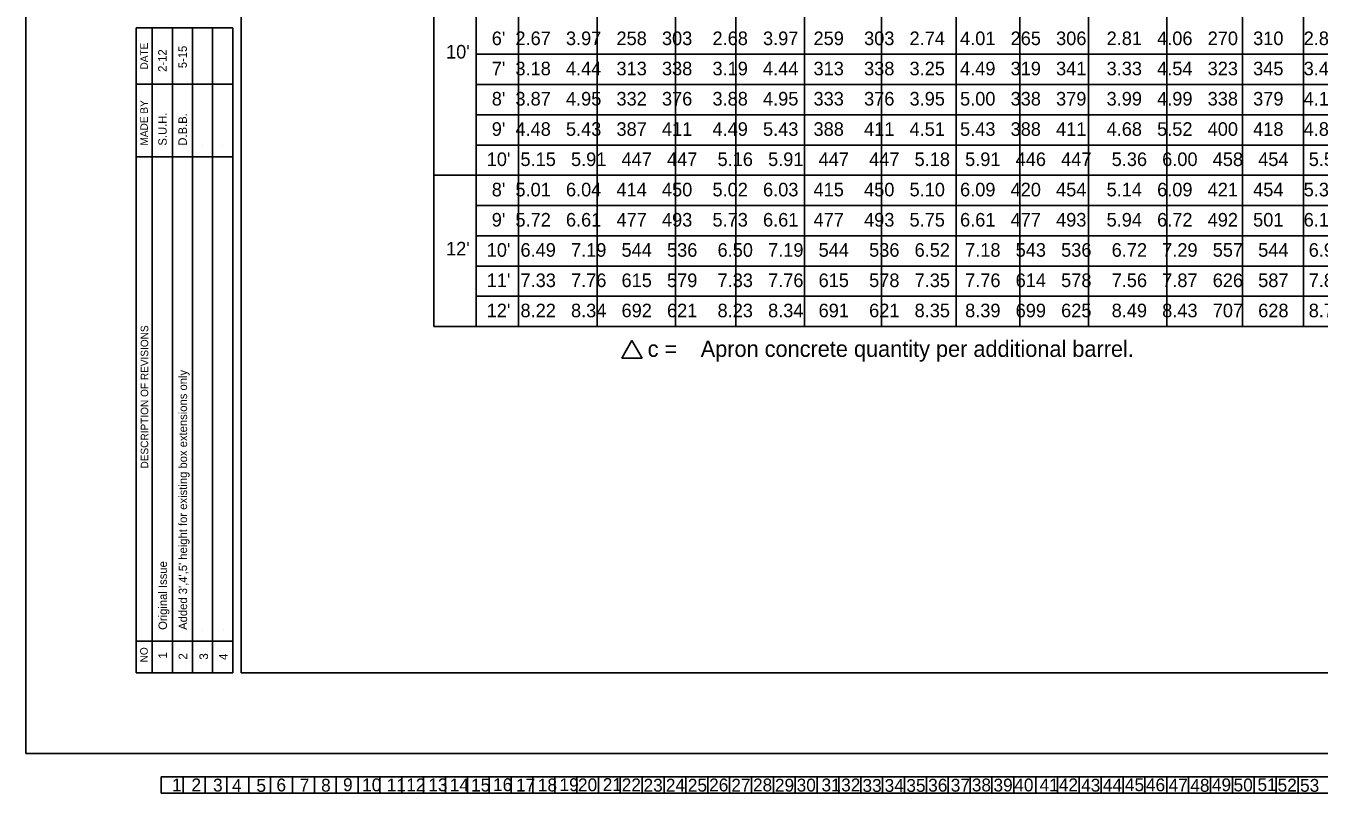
# Model space of a CAD drawing. Extents: x -0.08 to 2.83, y -0.03 to 1.92.
# Drawn here: x 0 to 1.002, y -0.031 to 0.564 of the extents above; entities that cross this region are included whole.
import ezdxf

# ---------------------------------------------------------------- set-up
doc = ezdxf.new("R2010")
doc.units = 0
for name, color, linetype in [('1', 7, 'Continuous'), ('10', 7, 'Continuous'), ('11', 7, 'Continuous'), ('12', 7, 'Continuous'), ('13', 7, 'Continuous'), ('14', 7, 'Continuous'), ('15', 7, 'Continuous'), ('16', 7, 'Continuous'), ('17', 7, 'Continuous'), ('18', 7, 'Continuous'), ('19', 7, 'Continuous'), ('2', 7, 'Continuous'), ('20', 7, 'Continuous'), ('21', 7, 'Continuous'), ('22', 7, 'Continuous'), ('23', 7, 'Continuous'), ('24', 7, 'Continuous'), ('25', 7, 'Continuous'), ('26', 7, 'Continuous'), ('27', 7, 'Continuous'), ('28', 7, 'Continuous'), ('29', 7, 'Continuous'), ('3', 7, 'Continuous'), ('30', 7, 'Continuous'), ('31', 7, 'Continuous'), ('32', 7, 'Continuous'), ('33', 7, 'Continuous'), ('34', 7, 'Continuous'), ('35', 7, 'Continuous'), ('36', 7, 'Continuous'), ('37', 7, 'Continuous'), ('38', 7, 'Continuous'), ('39', 7, 'Continuous'), ('4', 7, 'Continuous'), ('40', 7, 'Continuous'), ('41', 7, 'Continuous'), ('42', 7, 'Continuous'), ('43', 7, 'Continuous'), ('44', 7, 'Continuous'), ('45', 7, 'Continuous'), ('46', 7, 'Continuous'), ('47', 7, 'Continuous'), ('48', 7, 'Continuous'), ('49', 7, 'Continuous'), ('5', 7, 'Continuous'), ('50', 7, 'Continuous'), ('51', 7, 'Continuous'), ('52', 7, 'Continuous'), ('53', 7, 'Continuous'), ('55', 7, 'Continuous'), ('57', 7, 'Continuous'), ('6', 7, 'Continuous'), ('62', 7, 'Continuous'), ('63', 7, 'Continuous'), ('7', 7, 'Continuous'), ('8', 7, 'Continuous'), ('9', 7, 'Continuous')]:
    doc.layers.add(name, color=color, linetype=linetype)

msp = doc.modelspace()

# ---------------------------------------------------------------- linework, layer by layer
at = {"layer": '49'}
for p, q in [((0.6032, 0.9636), (0.6032, 0.3308)), ((0.8233, 0.9636), (0.8233, 0.3308)), ((0.3161, 0.448), (2.5857, 0.448))]:
    msp.add_line(p, q, dxfattribs=at)
at = {"layer": '55'}
for p, q in [((0.3161, 0.9949), (0.3161, 0.3308)), ((0.3489, 0.9636), (0.3489, 0.3308)), ((0.3817, 0.9636), (0.3817, 0.3308)), ((0.5033, 0.9402), (0.5033, 0.3308)), ((0.7208, 0.9402), (0.7208, 0.3308)), ((0.9426, 0.9402), (0.9426, 0.3308)), ((0.4426, 0.9168), (0.4426, 0.3308)), ((0.55, 0.9168), (0.55, 0.3308)), ((0.6628, 0.9168), (0.6628, 0.3308)), ((0.7701, 0.9168), (0.7701, 0.3308)), ((0.884, 0.9168), (0.884, 0.3308)), ((0.9897, 0.9168), (0.9897, 0.3308)), ((0.3489, 0.5418), (2.5857, 0.5418)), ((0.3489, 0.5183), (2.5857, 0.5183)), ((0.3489, 0.4949), (2.5857, 0.4949)), ((0.3489, 0.4714), (2.5857, 0.4714)), ((0.3489, 0.4246), (2.5857, 0.4246)), ((0.3489, 0.4011), (2.5857, 0.4011)), ((0.3489, 0.3777), (2.5857, 0.3777)), ((0.3489, 0.3543), (2.5857, 0.3543)), ((0.3161, 0.3308), (2.5857, 0.3308)), ((0.3489, 0.3308), (2.5857, 0.3308))]:
    msp.add_line(p, q, dxfattribs=at)
at = {"layer": '57'}
for p, q in [((0.4695, 0.3201), (0.4616, 0.3064)), ((0.4774, 0.3064), (0.4695, 0.3201)), ((0.4616, 0.3064), (0.4774, 0.3064))]:
    msp.add_line(p, q, dxfattribs=at)
at = {"layer": '62'}
for p, q in [((0.1058, 0.471), (0.1058, 0.471)), ((0.1219, 0.471), (0.1219, 0.471)), ((0.1372, 0.471), (0.1372, 0.471)), ((0.1525, 0.471), (0.1525, 0.471)), ((0.106, 0.0958), (0.106, 0.0958)), ((0.121, 0.0954), (0.121, 0.0954)), ((0.1367, 0.0954), (0.1367, 0.0954)), ((0.153, 0.0958), (0.153, 0.0958)), ((0.1049, -0.018), (1.1717, -0.018)), ((0.1049, -0.018), (0.1049, -0.0307)), ((0.1219, -0.018), (0.1219, -0.0307)), ((0.1388, -0.018), (0.1388, -0.0307)), ((0.1557, -0.018), (0.1557, -0.0307)), ((0.1727, -0.018), (0.1727, -0.0307)), ((0.1896, -0.018), (0.1896, -0.0307)), ((0.2065, -0.018), (0.2065, -0.0307)), ((0.2235, -0.018), (0.2235, -0.0307)), ((0.2404, -0.018), (0.2404, -0.0307)), ((0.2573, -0.018), (0.2573, -0.0307)), ((0.2743, -0.018), (0.2743, -0.0307)), ((0.2912, -0.018), (0.2912, -0.0307)), ((0.3081, -0.018), (0.3081, -0.0307)), ((0.3251, -0.018), (0.3251, -0.0307)), ((0.342, -0.018), (0.342, -0.0307)), ((0.3589, -0.018), (0.3589, -0.0307)), ((0.3759, -0.018), (0.3759, -0.0307)), ((0.3928, -0.018), (0.3928, -0.0307)), ((0.4097, -0.018), (0.4097, -0.0307)), ((0.4267, -0.018), (0.4267, -0.0307)), ((0.4436, -0.018), (0.4436, -0.0307)), ((0.4605, -0.018), (0.4605, -0.0307)), ((0.4775, -0.018), (0.4775, -0.0307)), ((0.4944, -0.018), (0.4944, -0.0307)), ((0.5113, -0.018), (0.5113, -0.0307)), ((0.5283, -0.018), (0.5283, -0.0307)), ((0.5452, -0.018), (0.5452, -0.0307)), ((0.5621, -0.018), (0.5621, -0.0307)), ((0.5791, -0.018), (0.5791, -0.0307)), ((0.596, -0.018), (0.596, -0.0307)), ((0.6129, -0.018), (0.6129, -0.0307)), ((0.6299, -0.018), (0.6299, -0.0307)), ((0.6468, -0.018), (0.6468, -0.0307)), ((0.6637, -0.018), (0.6637, -0.0307)), ((0.6807, -0.018), (0.6807, -0.0307)), ((0.6976, -0.018), (0.6976, -0.0307)), ((0.7145, -0.018), (0.7145, -0.0307)), ((0.7315, -0.018), (0.7315, -0.0307)), ((0.7484, -0.018), (0.7484, -0.0307)), ((0.7653, -0.018), (0.7653, -0.0307)), ((0.7823, -0.018), (0.7823, -0.0307)), ((0.7992, -0.018), (0.7992, -0.0307)), ((0.8161, -0.018), (0.8161, -0.0307)), ((0.8331, -0.018), (0.8331, -0.0307)), ((0.85, -0.018), (0.85, -0.0307)), ((0.8669, -0.018), (0.8669, -0.0307)), ((0.8839, -0.018), (0.8839, -0.0307)), ((0.9008, -0.018), (0.9008, -0.0307)), ((0.9177, -0.018), (0.9177, -0.0307)), ((0.9347, -0.018), (0.9347, -0.0307)), ((0.9516, -0.018), (0.9516, -0.0307)), ((0.9685, -0.018), (0.9685, -0.0307)), ((0.9855, -0.018), (0.9855, -0.0307)), ((0.1049, -0.0307), (1.1717, -0.0307))]:
    msp.add_line(p, q, dxfattribs=at)
at = {"layer": '63'}
for p, q in [((0, 0), (0, 1.8333)), ((0.0854, 0.0624), (0.0854, 0.5624)), ((0.0854, 0.5624), (0.1604, 0.5624)), ((0.0979, 0.0624), (0.0979, 0.5624)), ((0.1135, 0.0626), (0.1135, 0.5624)), ((0.1291, 0.0628), (0.1291, 0.5624)), ((0.1447, 0.0629), (0.1447, 0.5624)), ((0.1604, 0.5624), (0.1604, 0.0624)), ((0.0854, 0.5186), (0.1604, 0.5186)), ((0.0854, 0.4622), (0.1604, 0.4622)), ((0.0854, 0.0871), (0.1604, 0.0871)), ((0.1604, 0.0624), (0.0854, 0.0624)), ((2.8333, 0), (0, 0))]:
    msp.add_line(p, q, dxfattribs=at)
msp.add_lwpolyline([(0.1667, 0.0624), (0.1667, 1.7708), (2.7292, 1.7708), (2.7292, 0.1041), (2.5625, 0.1041), (2.5625, 0.1458), (2.0739, 0.1458), (2.0739, 0.0624)], close=True, dxfattribs=at)

# ---------------------------------------------------------------- texts
at = {"layer": '1'}
msp.add_text('1', height=0.01, rotation=360, dxfattribs=at).set_placement((0.1132, -0.0294))
at = {"layer": '10'}
msp.add_text('10', height=0.01, rotation=360, dxfattribs=at).set_placement((0.2605, -0.0293))
at = {"layer": '11'}
msp.add_text('11', height=0.01, rotation=360, dxfattribs=at).set_placement((0.2796, -0.0294))
at = {"layer": '12'}
msp.add_text('12', height=0.01, rotation=360, dxfattribs=at).set_placement((0.2947, -0.0293))
at = {"layer": '13'}
msp.add_text('13', height=0.01, rotation=360, dxfattribs=at).set_placement((0.3118, -0.0293))
at = {"layer": '14'}
msp.add_text('14', height=0.01, rotation=360, dxfattribs=at).set_placement((0.3284, -0.0294))
at = {"layer": '15'}
msp.add_text('15', height=0.01, rotation=360, dxfattribs=at).set_placement((0.3449, -0.0295))
at = {"layer": '16'}
msp.add_text('16', height=0.01, rotation=360, dxfattribs=at).set_placement((0.3619, -0.0292))
at = {"layer": '17'}
msp.add_text('17', height=0.01, rotation=360, dxfattribs=at).set_placement((0.3797, -0.0295))
at = {"layer": '18'}
msp.add_text('18', height=0.01, rotation=360, dxfattribs=at).set_placement((0.3966, -0.0294))
at = {"layer": '19'}
msp.add_text('19', height=0.01, rotation=360, dxfattribs=at).set_placement((0.4134, -0.0292))
at = {"layer": '2'}
msp.add_text('2', height=0.01, rotation=360, dxfattribs=at).set_placement((0.1283, -0.0293))
at = {"layer": '20'}
msp.add_text('20', height=0.01, rotation=360, dxfattribs=at).set_placement((0.4277, -0.0293))
at = {"layer": '21'}
msp.add_text('21', height=0.01, rotation=360, dxfattribs=at).set_placement((0.4469, -0.0291))
at = {"layer": '22'}
msp.add_text('22', height=0.01, rotation=360, dxfattribs=at).set_placement((0.4616, -0.0293))
at = {"layer": '23'}
msp.add_text('23', height=0.01, rotation=360, dxfattribs=at).set_placement((0.4785, -0.0296))
at = {"layer": '24'}
msp.add_text('24', height=0.01, rotation=360, dxfattribs=at).set_placement((0.4958, -0.0296))
at = {"layer": '25'}
msp.add_text('25', height=0.01, rotation=360, dxfattribs=at).set_placement((0.5128, -0.0296))
at = {"layer": '26'}
msp.add_text('26', height=0.01, rotation=360, dxfattribs=at).set_placement((0.5293, -0.0294))
at = {"layer": '27'}
msp.add_text('27', height=0.01, rotation=360, dxfattribs=at).set_placement((0.5465, -0.0296))
at = {"layer": '28'}
msp.add_text('28', height=0.01, rotation=360, dxfattribs=at).set_placement((0.5633, -0.0294))
at = {"layer": '29'}
msp.add_text('29', height=0.01, rotation=360, dxfattribs=at).set_placement((0.5803, -0.0296))
at = {"layer": '3'}
msp.add_text('3', height=0.01, rotation=360, dxfattribs=at).set_placement((0.145, -0.0295))
at = {"layer": '30'}
msp.add_text('30', height=0.01, rotation=360, dxfattribs=at).set_placement((0.5971, -0.0295))
at = {"layer": '31'}
msp.add_text('31', height=0.01, rotation=360, dxfattribs=at).set_placement((0.6164, -0.0294))
at = {"layer": '32'}
msp.add_text('32', height=0.01, rotation=360, dxfattribs=at).set_placement((0.6316, -0.0294))
at = {"layer": '33'}
msp.add_text('33', height=0.01, rotation=360, dxfattribs=at).set_placement((0.6481, -0.0298))
at = {"layer": '34'}
msp.add_text('34', height=0.01, rotation=360, dxfattribs=at).set_placement((0.6653, -0.0298))
at = {"layer": '35'}
msp.add_text('35', height=0.01, rotation=360, dxfattribs=at).set_placement((0.6821, -0.0298))
at = {"layer": '36'}
msp.add_text('36', height=0.01, rotation=360, dxfattribs=at).set_placement((0.699, -0.0296))
at = {"layer": '37'}
msp.add_text('37', height=0.01, rotation=360, dxfattribs=at).set_placement((0.7165, -0.0296))
at = {"layer": '38'}
msp.add_text('38', height=0.01, rotation=360, dxfattribs=at).set_placement((0.7328, -0.0294))
at = {"layer": '39'}
msp.add_text('39', height=0.01, rotation=360, dxfattribs=at).set_placement((0.7496, -0.0295))
at = {"layer": '4'}
msp.add_text('4', height=0.01, rotation=360, dxfattribs=at).set_placement((0.1597, -0.0298))
at = {"layer": '40'}
msp.add_text('40', height=0.01, rotation=360, dxfattribs=at).set_placement((0.7657, -0.0294))
at = {"layer": '41'}
msp.add_text('41', height=0.01, rotation=360, dxfattribs=at).set_placement((0.7853, -0.0294))
at = {"layer": '42'}
msp.add_text('42', height=0.01, rotation=360, dxfattribs=at).set_placement((0.8002, -0.0293))
at = {"layer": '43'}
msp.add_text('43', height=0.01, rotation=360, dxfattribs=at).set_placement((0.8175, -0.0296))
at = {"layer": '44'}
msp.add_text('44', height=0.01, rotation=360, dxfattribs=at).set_placement((0.8343, -0.0295))
at = {"layer": '45'}
msp.add_text('45', height=0.01, rotation=360, dxfattribs=at).set_placement((0.8514, -0.0292))
at = {"layer": '46'}
msp.add_text('46', height=0.01, rotation=360, dxfattribs=at).set_placement((0.8677, -0.0293))
at = {"layer": '47'}
msp.add_text('47', height=0.01, rotation=360, dxfattribs=at).set_placement((0.8852, -0.0296))
at = {"layer": '48'}
msp.add_text('48', height=0.01, rotation=360, dxfattribs=at).set_placement((0.9021, -0.0297))
at = {"layer": '49'}
msp.add_text('49', height=0.01, rotation=360, dxfattribs=at).set_placement((0.9188, -0.0293))
at = {"layer": '5'}
msp.add_text('5', height=0.01, rotation=360, dxfattribs=at).set_placement((0.1786, -0.0298))
at = {"layer": '50'}
msp.add_text('50', height=0.01, rotation=360, dxfattribs=at).set_placement((0.9356, -0.0294))
at = {"layer": '51'}
msp.add_text('51', height=0.01, rotation=360, dxfattribs=at).set_placement((0.9541, -0.0292))
at = {"layer": '52'}
msp.add_text('52', height=0.01, rotation=360, dxfattribs=at).set_placement((0.9697, -0.0295))
at = {"layer": '53'}
msp.add_text('53', height=0.01, rotation=360, dxfattribs=at).set_placement((0.9871, -0.0297))
at = {"layer": '57'}
for s, height, p in [(" 6'  2.67   3.97   258   303    2.68   3.97   259    303   2.74   4.01   265   306    2.81   4.06   270   310    2.89   4.11   275   314    3.53   4.06   324   310    4.19   4.06   374   311    4.81   4.07   420   312    5.48   4.11   473   315    6.23   4.21   525   324", 0.01053, (0.357, 0.5489)), ("10'", 0.01053, (0.3255, 0.5385)), (" 7'  3.18   4.44   313   338    3.19   4.44   313    338   3.25   4.49   319   341    3.33   4.54   323   345    3.48   4.63   335   352    4.19   4.52   389   344    4.93   4.52   444   345    5.57   4.46   491   341    6.43   4.54   557   347    7.31   4.64   612   356", 0.01053, (0.357, 0.5255)), (" 8'  3.87   4.95   332   376    3.88   4.95   333    376   3.95   5.00   338   379    3.99   4.99   338   379    4.16   5.08   351   386    5.02   5.03   415   383    5.93   5.02   486   382    6.77   5.01   551   382    7.63   5.06   613   386    8.69   5.16   690   394", 0.01053, (0.357, 0.5021)), (" 9'  4.48   5.43   387   411    4.49   5.43   388    411   4.51   5.43   388   411    4.68   5.52   400   418    4.87   5.60   412   425    5.79   5.50   482   417    6.80   5.49   560   417    7.74   5.48   630   417    8.73   5.49   704   418   10.04   5.67   789   432", 0.01053, (0.357, 0.4786)), ("10'  5.15   5.91   447   447    5.16   5.91   447    447   5.18   5.91   446   447    5.36   6.00   458   454    5.55   6.08   468   461    6.62   5.97   554   452    7.75   5.96   639   452    8.81   5.92   723   449   10.05   6.00   806   456   11.34   6.10   889   465", 0.01053, (0.357, 0.4552)), (" 8'  5.01   6.04   414   450    5.02   6.03   415    450   5.10   6.09   420   454    5.14   6.09   421   454    5.33   6.20   435   463    6.19   6.14   499   458    7.10   6.14   570   458    7.94   6.13   635   457    8.82   6.19   698   462    9.91   6.33   776   472", 0.01053, (0.357, 0.4317)), (" 9'  5.72   6.61   477   493    5.73   6.61   477    493   5.75   6.61   477   493    5.94   6.72   492   501    6.15   6.82   505   509    7.05   6.70   573   500    8.07   6.70   651   499    9.01   6.69   635   457   10.01   6.72   795   501   11.37   6.94   884   518", 0.01053, (0.357, 0.4083)), ("12'", 0.01053, (0.3255, 0.3859)), ("10'  6.49   7.19   544   536    6.50   7.19   544    536   6.52   7.18   543   536    6.72   7.29   557   544    6.93   7.40   569   552    7.99   7.26   653   541    9.11   7.25   737   541   10.17   7.22   821   538   11.44   7.32   905   546   12.76   7.46   991   557", 0.01053, (0.357, 0.3849)), ("11'  7.33   7.76   615   579    7.33   7.76   615    578   7.35   7.76   614   578    7.56   7.87   626   587    7.89   8.02   648   598    9.07   7.89   741   588   10.23   7.81   829   582   11.44   7.78   919   580   12.78   7.85  1016   585   14.23   7.98  1103   595", 0.01053, (0.357, 0.3614)), ("12'  8.22   8.34   692   621    8.23   8.34   691    621   8.35   8.39   699   625    8.49   8.43   707   628    8.72   8.54   717   636   10.02   8.40   818   626   11.49   8.37   927   624   12.77   8.34  1023   622   14.26   8.41  1124   627   16.08   8.16  1245   643", 0.01053, (0.357, 0.338)), ('c =', 0.01257, (0.4817, 0.3073)), ('Apron concrete quantity per additional barrel.', 0.012574, (0.5228, 0.3073))]:
    msp.add_text(s, height=height, dxfattribs=at).set_placement(p)
at = {"layer": '6'}
msp.add_text('6', height=0.01, rotation=360, dxfattribs=at).set_placement((0.1941, -0.0294))
at = {"layer": '62'}
for s, height, p in [(' 2-12', 0.00651, (0.109, 0.5258)), ('5-15', 0.00651, (0.1247, 0.531)), ('S.U.H.  ', 0.00651, (0.1091, 0.471)), ('D.B.B.', 0.00651, (0.1247, 0.471)), ("Added 3',4',5' height for existing box extensions only", 0.006508, (0.1249, 0.0958)), ('Original Issue                                                   ', 0.006508, (0.1093, 0.0958))]:
    msp.add_text(s, height=height, rotation=90, dxfattribs=at).set_placement(p)
at = {"layer": '63'}
for s, height, p in [('DATE', 0.00583, (0.0945, 0.53)), ('MADE BY', 0.00583, (0.0945, 0.4711)), ('DESCRIPTION OF REVISIONS', 0.005833, (0.0948, 0.2208)), ('NO', 0.00583, (0.0944, 0.0706)), ('1', 0.00667, (0.1094, 0.0735)), ('2', 0.00667, (0.125, 0.0727)), ('3', 0.00667, (0.1411, 0.0727)), ('4', 0.00667, (0.1564, 0.0724))]:
    msp.add_text(s, height=height, rotation=90, dxfattribs=at).set_placement(p)
at = {"layer": '7'}
msp.add_text('7', height=0.01, rotation=360, dxfattribs=at).set_placement((0.2121, -0.0296))
at = {"layer": '8'}
msp.add_text('8', height=0.01, rotation=360, dxfattribs=at).set_placement((0.2287, -0.0296))
at = {"layer": '9'}
msp.add_text('9', height=0.01, rotation=360, dxfattribs=at).set_placement((0.2457, -0.0292))

doc.saveas('drawing.dxf')
